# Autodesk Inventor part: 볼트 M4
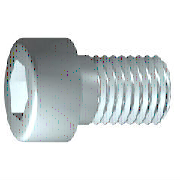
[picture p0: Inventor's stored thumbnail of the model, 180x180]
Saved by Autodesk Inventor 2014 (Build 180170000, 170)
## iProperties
IsCustomPart: 0
Created: 2012-02
Part Number: 볼트 M4
Material: 강철, 연강
Description: 6각 소켓 머리 캡 나사
Document SubType Name: Modeling
Standard: ISO 4762
Designer: mduedu
Standard Revision: Fourth edition 2004-03-01
Standards Organization: ISO
Language: ko-KR
Size Designation: M4 x 12
Categories: <MemberInstance><Categories><Category DisplayName="조임쇠" InternalName="e4da775c-781d-43d5-af7c-5136215cf5a6" Mnemonic="FSTN"><Category DisplayName="볼트" InternalN
Density: 7.75 g/cm^3
Appearance: 강철
Author: mduedu
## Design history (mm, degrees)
sketch "스케치1"
  geometry: L1 (-1, 0)-(12, 0); L2 (12, 0)-(12, 2); L3 (12, 2)-(1.75, 2); L4 (1.75, 2)-(1.32, 2); L5 (1.32, 2)-(0, 2); L6 (0, 2)-(0, 3.5); L7 (0, 3.5)-(-4, 3.5); L8 (-4, 3.5)-(-4, 1.732); L9 (-4, 1.732)-(-2, 1.732); L10 (-2, 1.732)-(-1, 0); L11 (-7.2, 0)-(15.2, 0) reference; L12 (0, -0.7)-(0, 4.2) reference; L13 (1.75, 2)-(0, 2)
  constraints: 22 end point, 6 parallel, 2 collinear, 2 perpendicular, 1 horizontal, 1 point on line
  dimensions: "d1" = 10.25 distance from line of L3.end L2 (= GEL); "d2" = 0.42952 distance of L4.end L3.end (computed from GAL); "d3" = 4 distance between parallel lines of L8 L6 (= KOH); "d4" = 2 distance of L8.end L9.end (= INTI); "d5" = 60 deg angle of L10 L1; "d6" = 4 diameter of L3 L1 (= GD); "d7" = 4 diameter of L5 L1 (= BDM); "d8" = 3.4641 diameter of L9 L1 (= 1.1547 x SW); "d9" = 7 diameter of L7 L1 (= KOD); "d26" = 12 distance between parallel lines of L12 L2 (= NLG)
revolve "본체" sketch "스케치1" stored, may be unused: angle "d10" = 90 deg
sketch "스케치2"
  geometry: L1 (0, -4.9)-(0, 4.9) reference; L2 (-4.9, 0)-(4.9, 0) reference; L3 (1.732, 0)-(0.866, -1.5); L4 (0.866, -1.5)-(-0.866, -1.5); L5 (-0.866, -1.5)-(-1.732, 0); L6 (-1.732, 0)-(-0.866, 1.5); L7 (-0.866, 1.5)-(0.866, 1.5); L8 (0.866, 1.5)-(1.732, 0); 2 further points
  constraints: 12 end point, 1 coincident, 1 horizontal alignment, 1 point on line, 12 other
extrude "슬롯" join sketch "스케치2" stored distance "d11" = 10; taper "d12" = 0 deg
workplane "Work Plane1"
fillet "Fillet2" dims "d30" = 0.1 (= R)
body "Solid1"
fillet "모깎기1" dims "d17" = 0.4 (= RR)
feature "스레드" dims "d13" = 10.25 (= GEL), "d14" = 0
chamfer "모따기1" distance "d15" = 0.42941 (= -0.5 x SPD + 0.5 x GD); stored, may be unused: second distance "d16" = 0.42941 (= GUL), angle "d27" = 45 deg
other parameters: "GD" = 4 [user parameter; used in 2 equation terms], "NLG" = 12 [user parameter; used in 1 equation term], "GEL" = 10.25 [user parameter; used in 2 equation terms], "KOD" = 7 [user parameter; used in 1 equation term], "KOH" = 4 [user parameter; used in 1 equation term], "INTI" = 2 [user parameter; used in 1 equation term], "GAL" = 0.42941 (= 0.61345 x PTC) [user parameter; used in 1 equation term], "GUL" = 0.42941 (= 0.61345 x PTC) [user parameter; used in 1 equation term], "BDM" = 4 (= NND) [user parameter; used in 1 equation term], "SW" = 3 [user parameter; used in 2 equation terms], "RR" = 0.4 [user parameter; used in 1 equation term], "SPD" = 3.14117 (= NND - 1.2269 x PTC) [user parameter; used in 1 equation term], "d19" = 0, "d28" = 0, "d29" = 0, "R" = 0.1 [user parameter; used in 1 equation term], "TOA" = 30 deg [user parameter], "GD1" = 3.14117 (= THREADDIA - 1.2269 x PTC) [user parameter], "THREADDIA" = 4 [user parameter; used in 1 equation term], "FAWI" = 45 deg [user parameter], "TPU" = 14.28571 (computed from PTC) [user parameter], "PTC" = 0.7 [user parameter; used in 5 equation terms], "NND" = 4 [user parameter; used in 2 equation terms], "E0" = 3.465 (= 1.155 x SW) [user parameter]
